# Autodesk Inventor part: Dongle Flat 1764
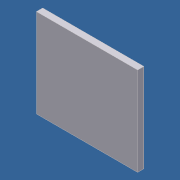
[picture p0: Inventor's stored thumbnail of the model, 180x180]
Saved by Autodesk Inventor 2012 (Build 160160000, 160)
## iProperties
Created: 2010-01
Part Number: Dongle Flat 1764
Document SubType Name: Modeling
Designer: jgehrig
Density: 1 g/cm^3
Material: Default
Author: jgehrig
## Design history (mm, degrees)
sketch "Sketch1"
  geometry: L1 (-3.179, 4.629)-(6.981, 4.629); L2 (6.981, 4.629)-(6.981, -4.261); L3 (6.981, -4.261)-(-3.179, -4.261); L4 (-3.179, -4.261)-(-3.179, 4.629); 1 further point
  constraints: 8 end point, 2 parallel, 1 horizontal, 1 perpendicular
  dimensions: "d0" = 8.89 distance of L1.end L2.end; "d1" = 10.16 distance of L2.end L3.end
extrude "Extrusion1" new body sketch "Sketch1" distance "d2" = 0.635; taper "d3" = 0 deg
body "Solid1"
